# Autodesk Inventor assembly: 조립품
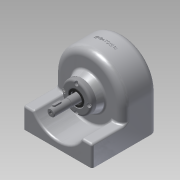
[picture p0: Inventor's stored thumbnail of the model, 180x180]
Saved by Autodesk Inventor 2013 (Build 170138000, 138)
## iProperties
Created: 2015-02
Part Number: 조립품
Document SubType Name: Assembly
Designer: Administrator
Author: Administrator
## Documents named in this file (10)
- C:\Users\Administrator\Desktop\450216V1023\조립품.iam
- C:\Users\Administrator\Desktop\450216V1023\본체.ipt
- C:\Users\Administrator\Desktop\450216V1023\축커버.ipt
- C:\Users\Administrator\Desktop\450216V1023\베어링 6001.ipt
- C:\Users\Administrator\Desktop\450216V1023\오일실.ipt
- C:\Users\Administrator\Desktop\450216V1023\축.ipt
- C:\Users\Administrator\Desktop\450216V1023\키5x5.ipt
- C:\Users\Administrator\Desktop\450216V1023\키4x4.ipt
- C:\Users\Administrator\Desktop\450216V1023\스퍼기어.ipt
- C:\Users\Administrator\Desktop\450216V1023\M3x0.5.ipt
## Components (1 placed, 1 different names)
1. M3x0.5:1
